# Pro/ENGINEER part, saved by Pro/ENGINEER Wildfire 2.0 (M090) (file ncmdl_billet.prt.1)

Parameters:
  NCX_STOCK_TYPE = "BILLET"

Other parameters: WP_X, WP_Y, WP_Z

Family table entries: ?0 , D10, PRO_MP_SOURCE, ~"x, GEOMETRY, 3GEOMETRY, MP_DENSITY, ~"x, value(NO_val), PRO_MP_ALT_MASS, ~"x, PRO_MP_ALT_VOLUME, ~"x, PRO_MP_ALT_AREA, ~"x, PRO_MP_ALT_COGX, ~"x, PRO_MP_ALT_COGY, ~"x, PRO_MP_ALT_COGZ, ~"x, PRO_MP_ALT_IXX, ~"x, PRO_MP_ALT_IYY, ~"x, PRO_MP_ALT_IZZ, ~"x, PRO_MP_ALT_IXZ, ~"x, PRO_MP_ALT_IYZ, ~"x, PRO_MP_ALT_IXY, ~"x, PRO_MP_MASS, PRO_MP_VOLUME, PRO_MP_DENSITY, PRO_MP_AREA, PRO_MP_COGX, PRO_MP_COGY, PRO_MP_COGZ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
